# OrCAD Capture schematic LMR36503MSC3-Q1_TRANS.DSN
size Custom; title: LMR36503MSC3-Q1 3 V–65 V, 0.3-A Synchronous Buck; rev: 1.0; note: Datasheet: SNVSBB5A        EVM: SNVU670A
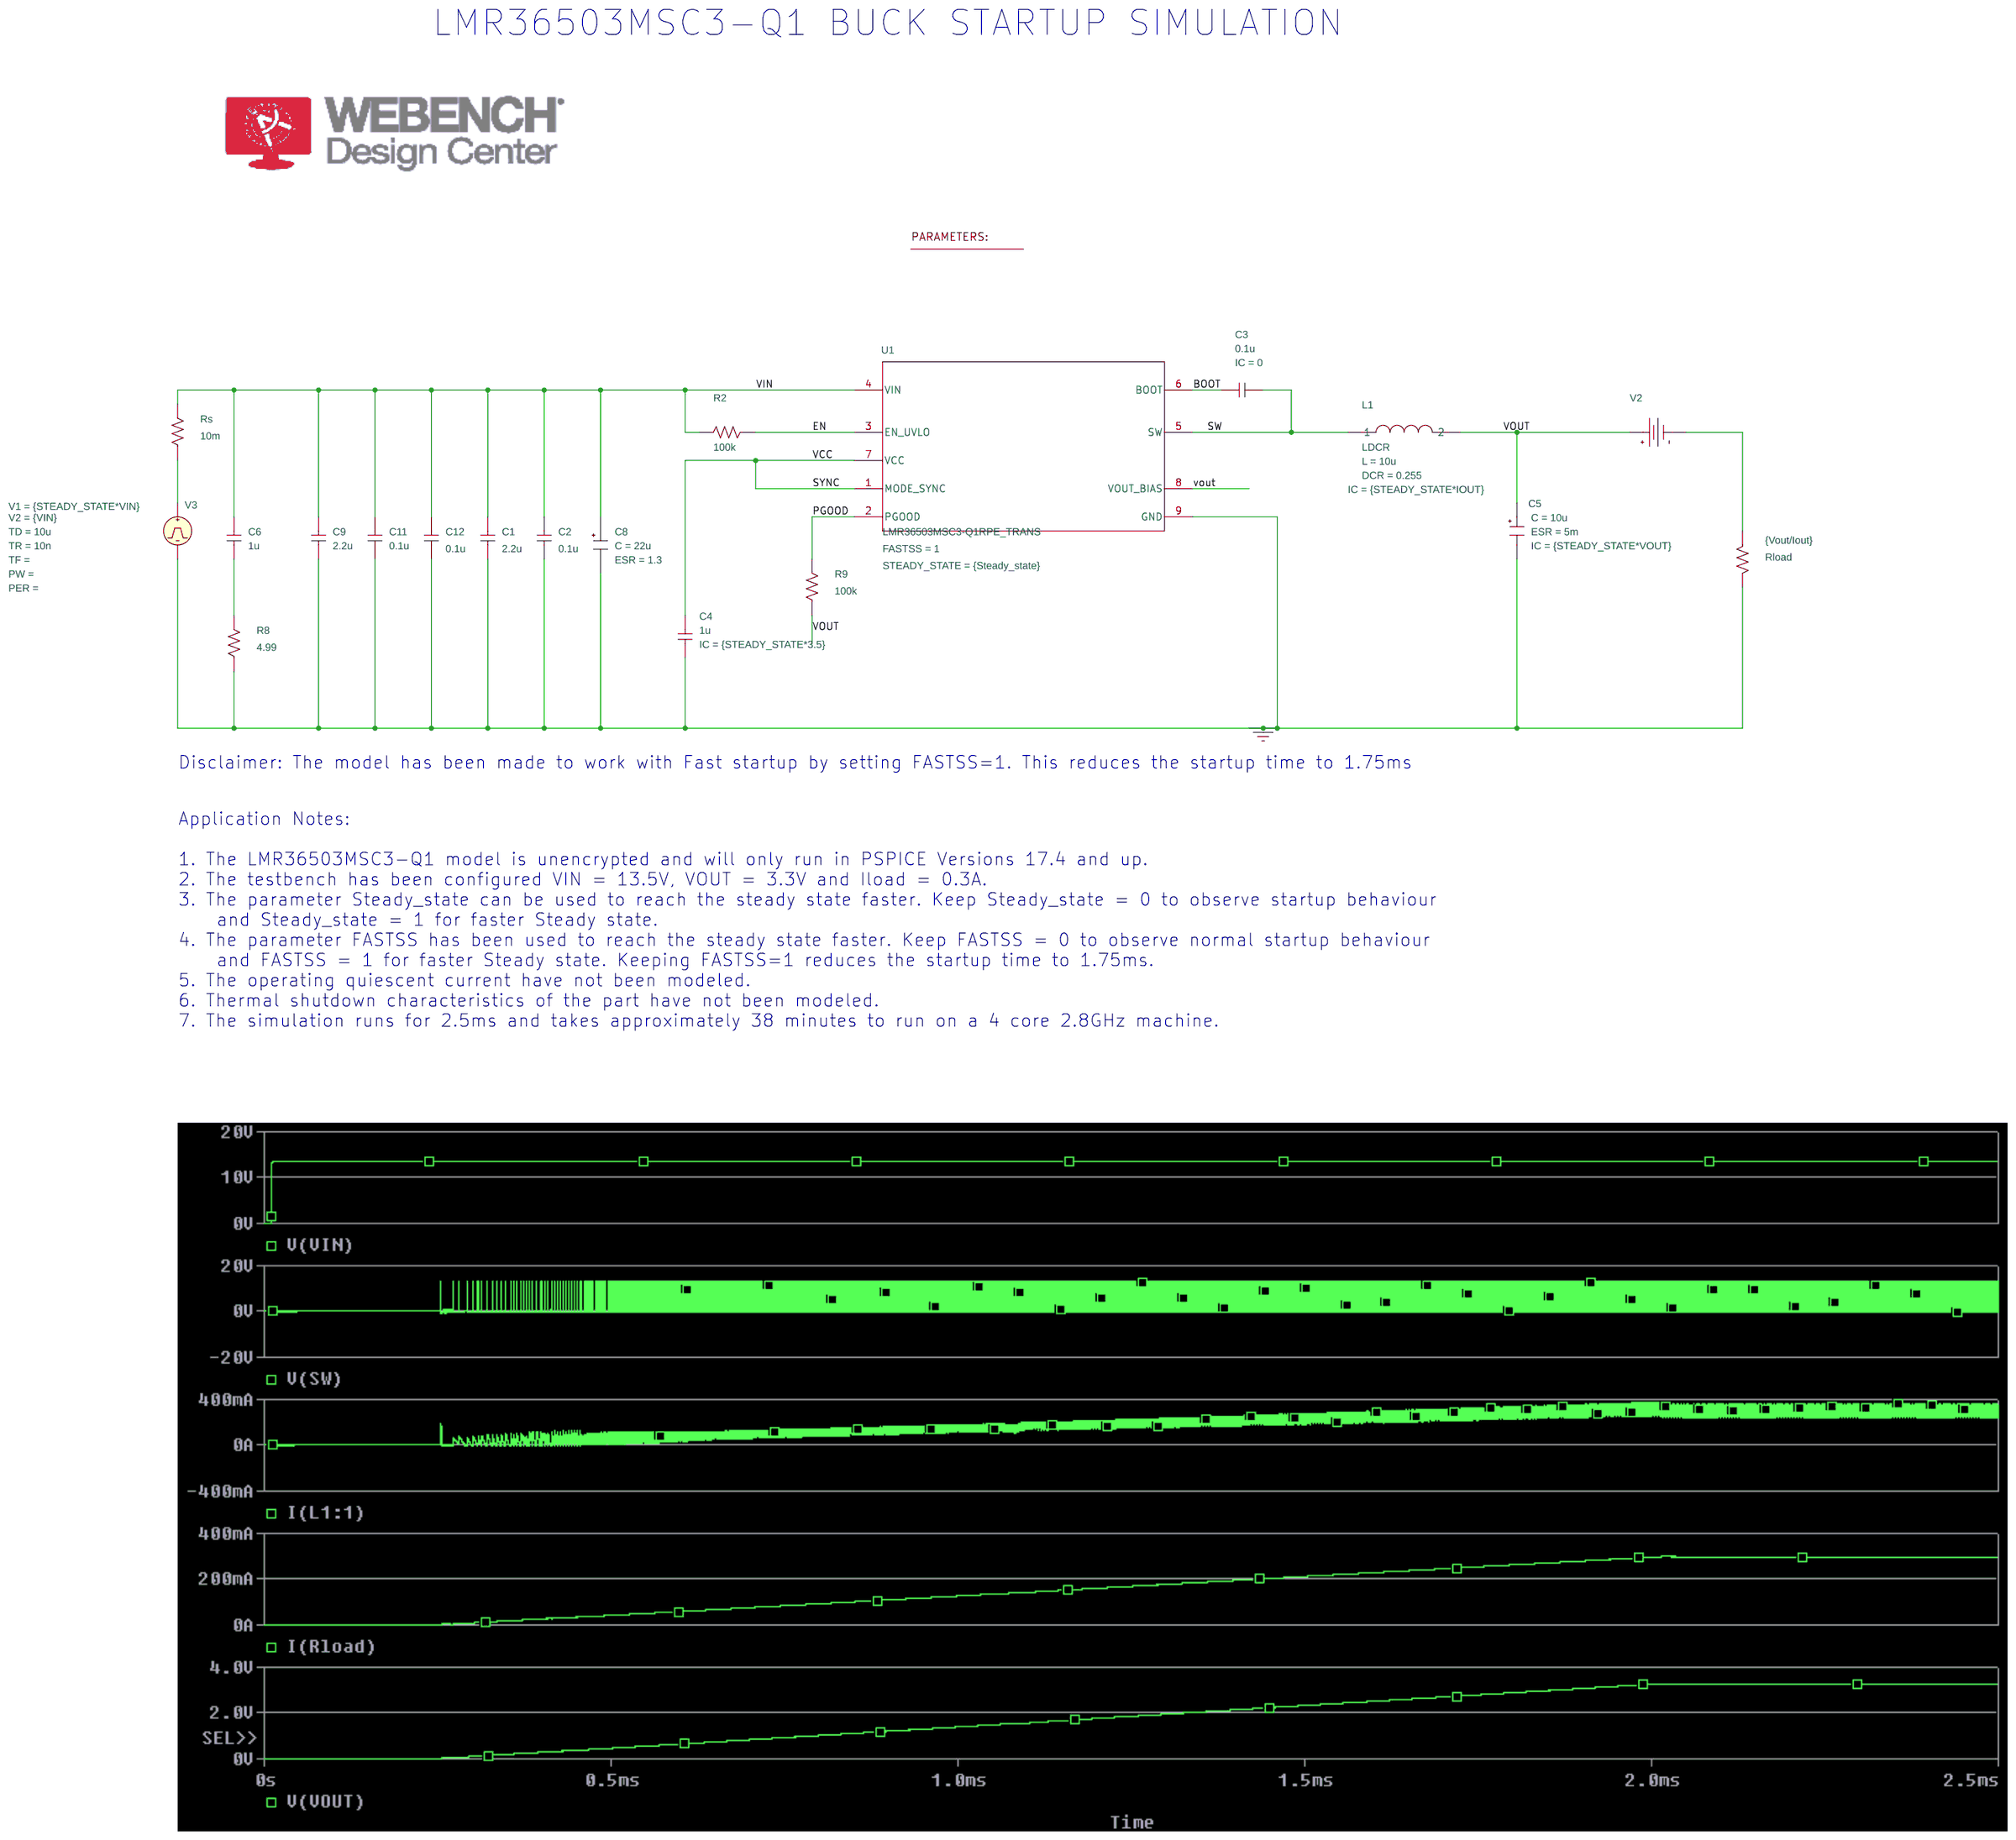
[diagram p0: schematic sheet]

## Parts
4  PARAM
C1  2.2u  [RAD/CK05]
C2  0.1u  [RAD/CK05]
C3  0.1u  [CK05]
C4  1u  [RAD/CK05]
C5  CESR
C6  1u  [RAD/CK05]
C8  CESR
C9  2.2u  [RAD/CK05]
C11  0.1u  [RAD/CK05]
C12  0.1u  [RAD/CK05]
L1  LDCR
R2  100k  [AX/RC05]
R8  4.99  [RC05]
R9  100k  [RC05]
Rload  {Vout/Iout}  [AX/RC05]
Rs  10m  [AX/RC05]
U1  LMR36503MSC3-Q1RPE_TRANS  [RPE0009A]
V2  VDC
V3  VPULSE

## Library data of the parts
4 = PARAM: IOUT: 0.3; STEADY_STATE: 0; VIN: 13.5; vout: 3.3
C1 C2 C6 C9 C11 C12 = C
C3 = C: IC: 0
C4 = C: IC: {STEADY_STATE*3.5}
C5 = CESR_0: C: 10u; ESR: 5m; IC: {STEADY_STATE*VOUT}; PSpiceTemplate: X^@REFDES %IN %OUT @MODEL PARAMS:  ?C|C=@C||C=100u|  ?ESR|ESR=@ESR||ESR=0.01| ?X|X=@X||X=2|  ?IC|IC=@IC||IC=2|; X: 1
C8 = CESR_0: C: 22u; ESR: 1.3; IC: {STEADY_STATE*VIN}; PSpiceTemplate: X^@REFDES %IN %OUT @MODEL PARAMS:  ?C|C=@C||C=100u|  ?ESR|ESR=@ESR||ESR=0.01| ?X|X=@X||X=2|  ?IC|IC=@IC||IC=2|; X: 1
L1 = LDCR: DCR: 0.255; IC: {STEADY_STATE*IOUT}; L: 10u; PSpiceTemplate: X^@REFDES %1 %2 @MODEL PARAMS: ?L|L=@L||L=10U| ?DCR|DCR=@DCR||DCR=20M| ?IC|IC=@IC||IC=0|
R2 R8 R9 Rload Rs = R
U1 = LMR36503MSC3-Q1RPE_TRANS: FASTSS: 1; STEADY_STATE: {Steady_state}
V2 = VDC
V3 = VPULSE: TD: 10u; TR: 10n; V1: {STEADY_STATE*VIN}; V2: {VIN}

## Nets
VIN: C1.2 C2.2 C6.2 C8.1(IN) C9.2 C11.2 C12.2 R2.2 Rs.2 U1.4(VIN)
0: C1.1 C2.1 C4.2 C5.2(OUT) C8.2(OUT) C9.1 C11.1 C12.1 R8.1 Rload.2 U1.9(GND) V3.2(-)
BOOT: C3.1 U1.6(BOOT)
EN: R2.1 U1.3(EN_UVLO)
PGOOD: R9.2 U1.2(PGOOD)
SW: C3.2 L1.1 U1.5(SW)
SYNC: C4.1 U1.1(MODE_SYNC) U1.7(VCC)
VOUT: C5.1(IN) L1.2 R9.1 U1.8(VOUT_BIAS) V2.0(+)
N263776: Rload.1 V2.1(-)
N264244: C6.1 R8.2
N264408: Rs.1 V3.1(+)

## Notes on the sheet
- LMR36503MSC3-Q1 BUCK STARTUP SIMULATION
- Disclaimer: The model has been made to work with Fast startup by setting FASTSS=1. This reduces the startup time to 1.75ms
- Application Notes:
  1. The LMR36503MSC3-Q1 model is unencrypted and will only run in PSPICE Versions 17.4 and up.
  2. The testbench has been configured VIN = 13.5V, VOUT = 3.3V and Iload = 0.3A.
  3. The parameter Steady_state can be used to reach the steady state faster. Keep Steady_state = 0 to observe startup behaviour
      and Steady_state = 1 for faster Steady state.
  4. The parameter FASTSS has been used to reach the steady state faster. Keep FASTSS = 0 to observe normal startup behaviour
      and FASTSS = 1 for faster Steady state. Keeping FASTSS=1 reduces the startup time to 1.75ms.
  5. The operating quiescent current have not been modeled.
  6. Thermal shutdown characteristics of the part have not been modeled.
  7. The simulation runs for 2.5ms and takes approximately 38 minutes to run on a 4 core 2.8GHz machine.
